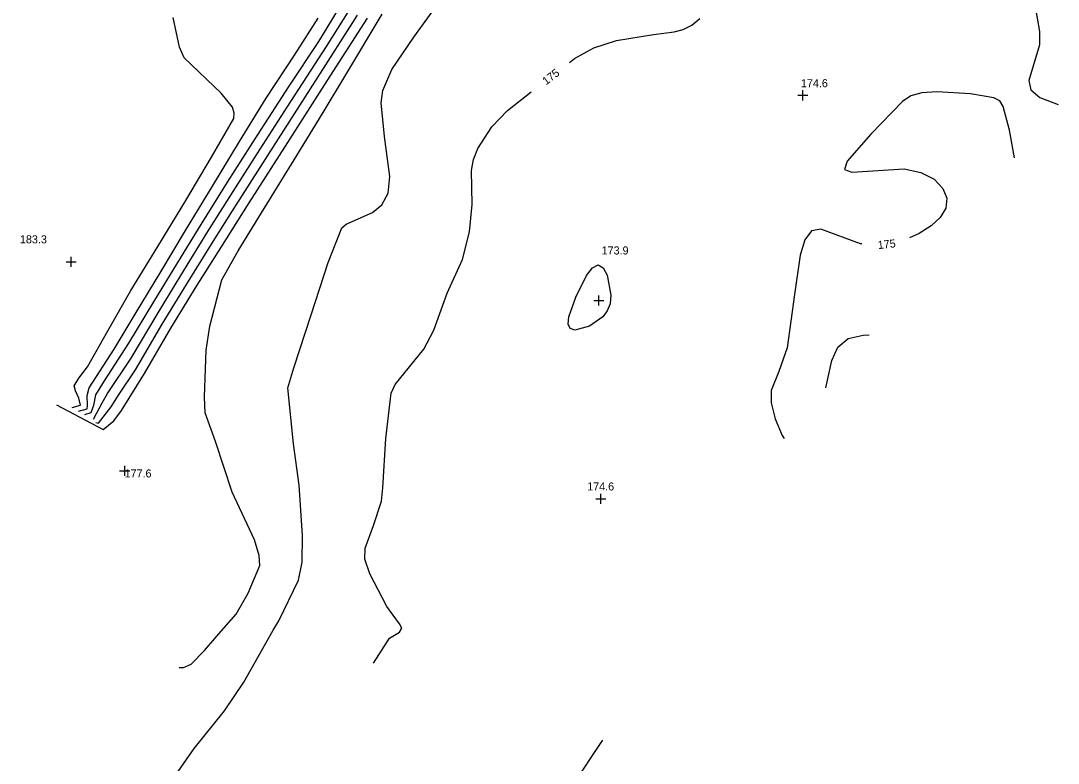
# Model space of a CAD drawing. Extents: x 1475150 to 2003689, y 770235 to 1112803.
# Drawn here: x 1996005.7 to 1996263.4, y 776984.1 to 777168.5 of the extents above; entities that cross this region are included whole.
import ezdxf

# ---------------------------------------------------------------- set-up
doc = ezdxf.new("R2010")
doc.units = 0
for name, color, linetype in [('RD_DTM_Major1', 7, 'Continuous'), ('RD_DTM_Major1_Lbl', 7, 'Continuous'), ('RD_DTM_Minor1', 7, 'Continuous'), ('RD_DTM_Spot_Elev', 7, 'Continuous')]:
    doc.layers.add(name, color=color, linetype=linetype)

msp = doc.modelspace()

# ---------------------------------------------------------------- linework, layer by layer
at = {"layer": 'RD_DTM_Major1'}
for points in [[(1996023.79, 777069.55), (1996025.97, 777073.58), (1996027.25, 777075.94), (1996033.14, 777084.68), (1996039.83, 777095.94), (1996045.49, 777105.24), (1996052.2, 777116.13), (1996059.08, 777126.99), (1996064.49, 777135.45), (1996071.9, 777147.07), (1996081.64, 777162.14), (1996088.74, 777173.32)], [(1996257.65, 777172.48), (1996258.77, 777165.83), (1996258.79, 777162.58), (1996256.13, 777153.68), (1996256.65, 777151.34), (1996258.9, 777149.46), (1996263.44, 777147.69)], [(1996142.02, 777158.19), (1996143.3, 777159.17), (1996148.1, 777161.8), (1996153.75, 777163.64), (1996162.91, 777165.11), (1996168.03, 777165.76), (1996170.28, 777166.38), (1996172.39, 777167.43), (1996174.4, 777169.06)], [(1996093.36, 777008.91), (1996097.34, 777015.16), (1996099.77, 777016.6), (1996100.35, 777017.63), (1996099.8, 777018.73), (1996096.68, 777023.02), (1996092.46, 777031.16), (1996091.2, 777034.75), (1996091.26, 777037.5), (1996093.32, 777043.11), (1996095.32, 777049.14), (1996095.71, 777052.51), (1996096.39, 777064.75), (1996097.75, 777076.04), (1996098.71, 777078.18), (1996105.85, 777086.94), (1996108.31, 777091.63), (1996111.68, 777100.84), (1996115.44, 777109.2), (1996117.21, 777116.06), (1996117.89, 777122.89), (1996117.69, 777131.36), (1996118.17, 777134.05), (1996119.26, 777136.83), (1996122.75, 777142.18), (1996126.67, 777146.27), (1996132.53, 777150.84)], [(1996252.61, 777134.5), (1996251.34, 777141.32), (1996249.79, 777147.2), (1996248.89, 777148.6), (1996247.45, 777149.37), (1996241.63, 777150.33), (1996233.27, 777150.87), (1996229.59, 777150.62), (1996226.86, 777149.85), (1996224.73, 777148.48), (1996216.86, 777140.34), (1996211.04, 777133.68), (1996210.37, 777131.59), (1996212.14, 777130.91), (1996225.19, 777131.75), (1996229.33, 777130.85), (1996232.58, 777129.13), (1996234.78, 777126.89), (1996235.79, 777124.42), (1996235.52, 777121.98), (1996234.13, 777119.68), (1996231.86, 777117.57), (1996228.92, 777115.71), (1996226.53, 777114.62)], [(1996214.63, 777113.1), (1996214.33, 777113.13), (1996204.5, 777116.77), (1996202.17, 777116.36), (1996200.47, 777114.08), (1996199.31, 777110.28), (1996197.92, 777100.52), (1996196.12, 777087.25), (1996194.01, 777081.39), (1996192.11, 777076.68), (1996192.11, 777073.58), (1996193.1, 777069.59), (1996194.83, 777065.47), (1996195.32, 777064.73)], [(1996205.7, 777077.37), (1996207.16, 777084.16), (1996208.73, 777087.43), (1996211.25, 777089.56), (1996214.98, 777090.45), (1996216.48, 777090.5)]]:
    msp.add_lwpolyline(points, dxfattribs=at)
at = {"layer": 'RD_DTM_Minor1'}
for points in [[(1996021.69, 777070.7), (1996023.21, 777071.19), (1996023.87, 777073.06), (1996024.34, 777075.6), (1996026.56, 777079.08), (1996032.6, 777088.44), (1996038.75, 777098.73), (1996044.71, 777108.48), (1996050.51, 777117.91), (1996057.11, 777128.43), (1996064.7, 777140.32), (1996072.38, 777152.26), (1996079.8, 777163.35), (1996087.01, 777175.28)], [(1996043.65, 776980.38), (1996048.77, 776987.75), (1996056.38, 776997.11), (1996061.16, 777004.2), (1996068.44, 777017.14), (1996069.85, 777019.48), (1996074.74, 777029.51), (1996075.67, 777034.01), (1996075.73, 777040.65), (1996074.89, 777053.14), (1996073.49, 777063.39), (1996072.05, 777077.33), (1996073.55, 777082.29), (1996077.84, 777095.45), (1996082.13, 777108.47), (1996085.51, 777117.1), (1996086.56, 777118), (1996093.11, 777120.86), (1996095.46, 777122.8), (1996097, 777125.73), (1996097.38, 777129.84), (1996096.09, 777139.73), (1996095.27, 777148.15), (1996095.69, 777151.24), (1996097.88, 777156.4), (1996103.34, 777164.41), (1996109.69, 777173.13)], [(1996014.65, 777073.12), (1996026.2, 777066.97), (1996028.86, 777069.1), (1996030.76, 777071.66), (1996036.49, 777080.91), (1996043.04, 777092.16), (1996049.55, 777102.82), (1996055.41, 777112.15), (1996062.48, 777123.25), (1996072.06, 777138.26), (1996081.88, 777153.57), (1996091.84, 777169.15)], [(1996018.48, 777072.44), (1996020.54, 777073.06), (1996020.15, 777074.76), (1996019.34, 777076.62), (1996018.96, 777077.83), (1996020.19, 777079.72), (1996022.35, 777082.53), (1996027.38, 777091.53), (1996033.08, 777101.53), (1996039.75, 777112.42), (1996046.71, 777123.89), (1996053.13, 777134.67), (1996058.66, 777144.26), (1996058.77, 777145.57), (1996058.34, 777147.09), (1996055.5, 777150.56), (1996046.36, 777159.34), (1996045.19, 777161.99), (1996043.63, 777169.36)], [(1996020.11, 777071.56), (1996022.23, 777072.12), (1996022.31, 777072.95), (1996022.26, 777075.45), (1996022.75, 777077.31), (1996028.95, 777086.93), (1996034.39, 777096.04), (1996040.49, 777106.12), (1996046.67, 777116.38), (1996053.1, 777127.02), (1996060.08, 777138.56), (1996066.71, 777149.31), (1996073.74, 777159.95), (1996079.57, 777169.13)], [(1996024.37, 777068.75), (1996025.02, 777068.53), (1996028.17, 777072.62), (1996030.03, 777075.49), (1996034.2, 777081.8), (1996040.88, 777093.13), (1996046.91, 777103.03), (1996053.49, 777113.67), (1996058.33, 777121.27), (1996067.13, 777135.07), (1996078.99, 777153.69), (1996089.39, 777169.89)], [(1996045.11, 777007.86), (1996046.16, 777007.87), (1996048.1, 777008.71), (1996051.35, 777012.05), (1996054.92, 777016.18), (1996059.28, 777021.11), (1996062.26, 777026.31), (1996065.11, 777033.23), (1996064.97, 777035.7), (1996063.79, 777039.54), (1996058.22, 777051.41), (1996054.09, 777063.96), (1996051.55, 777071.11), (1996051.4, 777075.03), (1996051.82, 777086.69), (1996052.69, 777092.63), (1996055.64, 777104.19), (1996059.76, 777111.36), (1996065.5, 777120.83), (1996074.27, 777135.06), (1996080.88, 777145.74), (1996086.72, 777155.49), (1996095.54, 777170.18)], [(1996149.13, 777107.87), (1996150.38, 777107.14), (1996151.39, 777105.3), (1996152.34, 777100.39), (1996152.12, 777098.23), (1996151.43, 777096.44), (1996150.31, 777094.95), (1996146.97, 777092.64), (1996143.38, 777091.66), (1996142.19, 777092.05), (1996141.72, 777093.17), (1996141.9, 777094.95), (1996143.62, 777099.88), (1996146.3, 777105.27), (1996147.74, 777107.15), (1996149.13, 777107.87)], [(1996125.92, 776966.23), (1996126.87, 776967.1), (1996134.13, 776972.88), (1996143.39, 776979.33), (1996149.73, 776989), (1996150.32, 776989.76)]]:
    msp.add_lwpolyline(points, dxfattribs=at)
at = {"layer": 'RD_DTM_Spot_Elev'}
for p, q in [((1996200, 777148.75), (1996200, 777151.25)), ((1996198.75, 777150), (1996201.25, 777150)), ((1996018.26, 777107.38), (1996018.26, 777109.88)), ((1996017.01, 777108.63), (1996019.51, 777108.63)), ((1996149.3, 777097.81), (1996149.3, 777100.31)), ((1996148.05, 777099.06), (1996150.55, 777099.06)), ((1996031.55, 777055.46), (1996031.55, 777057.96)), ((1996030.3, 777056.71), (1996032.8, 777056.71)), ((1996149.84, 777048.53), (1996149.84, 777051.03)), ((1996148.59, 777049.78), (1996151.09, 777049.78))]:
    msp.add_line(p, q, dxfattribs=at)

# ---------------------------------------------------------------- texts
at = {"layer": 'RD_DTM_Major1_Lbl'}
for rotation, p in [(37.538, (1996136.23, 777152.47)), (6.1136, (1996218.71, 777111.78))]:
    msp.add_text('175', height=2, rotation=rotation, dxfattribs=at).set_placement(p)
at = {"layer": 'RD_DTM_Spot_Elev'}
for s, p in [('174.6', (1996199.52, 777152.01)), ('183.3', (1996005.53, 777113.22)), ('173.9', (1996150.01, 777110.46)), ('177.6', (1996031.52, 777055.06)), ('174.6', (1996146.43, 777051.83))]:
    msp.add_text(s, height=2, dxfattribs=at).set_placement(p)

doc.saveas('drawing.dxf')
